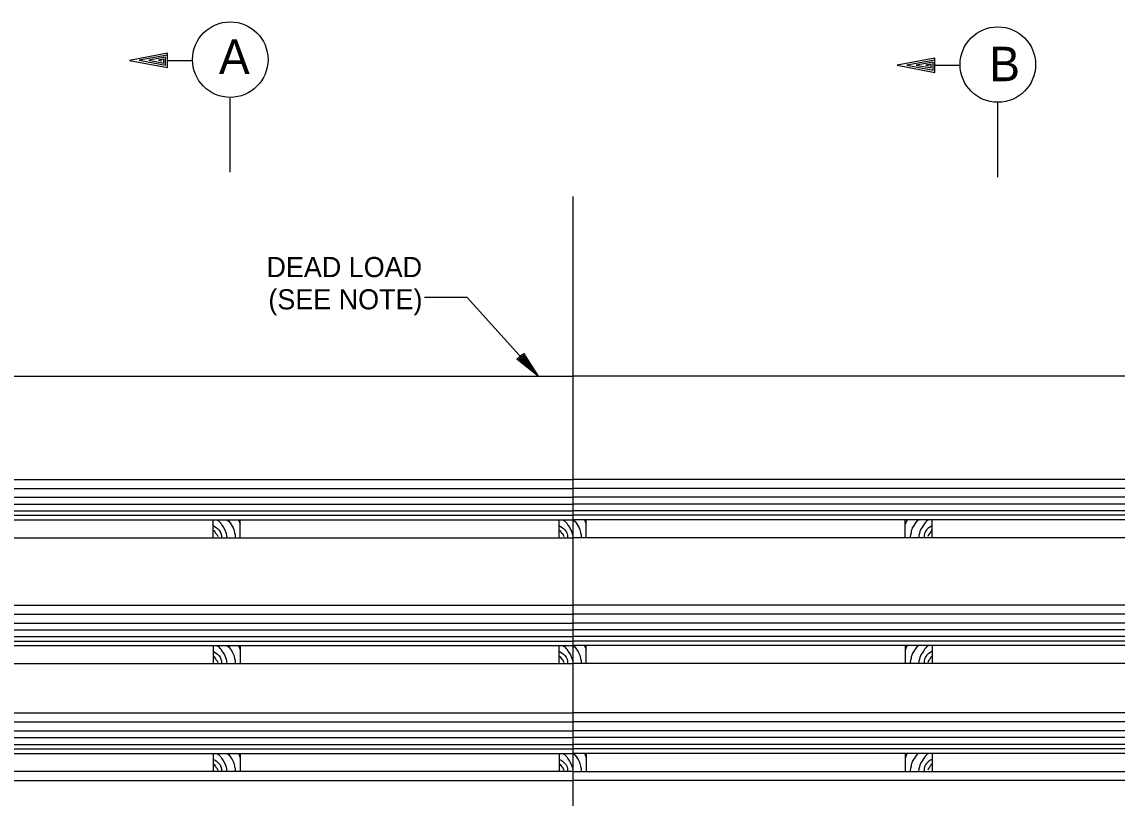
# Model space of a CAD drawing. Extents: x 22378.6 to 22422.6, y 22377.7 to 22411.7.
# Drawn here: x 22385.54 to 22393.16, y 22389.06 to 22394.46 of the extents above; entities that cross this region are included whole.
import ezdxf

# ---------------------------------------------------------------- set-up
doc = ezdxf.new("R2010")
doc.units = 0
for name, color, linetype in [('Level 1', 7, 'Continuous'), ('Level 2', 7, 'Continuous'), ('Level 3', 7, 'Continuous'), ('Level 4', 7, 'Continuous'), ('Level 7', 7, 'Continuous')]:
    doc.layers.add(name, color=color, linetype=linetype)

msp = doc.modelspace()

# ---------------------------------------------------------------- linework, layer by layer
at = {"layer": 'Level 1'}
for p, q in [((22389.3753, 22393.2465), (22389.3753, 22383.2487)), ((22389.1, 22392.0367), (22389.1, 22392.0367)), ((22389.1349, 22391.9982), (22389.1349, 22391.9982)), ((22383.1253, 22391.0607), (22389.3753, 22391.0607)), ((22395.6253, 22391.0607), (22389.3753, 22391.0607)), ((22383.1253, 22391.0295), (22389.3753, 22391.0295)), ((22395.6253, 22391.0295), (22389.3753, 22391.0295)), ((22383.1253, 22390.1857), (22389.3753, 22390.1857)), ((22383.1253, 22390.1545), (22389.3753, 22390.1545)), ((22395.6253, 22390.1857), (22389.3753, 22390.1857)), ((22395.6253, 22390.1545), (22389.3753, 22390.1545)), ((22383.1253, 22389.4357), (22389.3753, 22389.4357)), ((22383.1253, 22389.4045), (22389.3753, 22389.4045)), ((22395.6253, 22389.4357), (22389.3753, 22389.4357)), ((22395.6253, 22389.4045), (22389.3753, 22389.4045))]:
    msp.add_line(p, q, dxfattribs=at)
for points in [[(22389.1349, 22391.9982), (22388.6399, 22392.5435), (22388.3436, 22392.5435)], [(22389.0322, 22392.1575), (22389.1349, 22391.9982), (22388.9863, 22392.1159), (22389.0255, 22392.1515), (22389.1, 22392.0367), (22388.9991, 22392.1166), (22389.0242, 22392.1395), (22389.0664, 22392.0737), (22389.0119, 22392.1174), (22389.0222, 22392.1269), (22389.0314, 22392.1122)], [(22386.9031, 22390.9946), (22386.912, 22390.9913), (22386.9194, 22390.9834), (22386.9269, 22390.9746), (22386.9353, 22390.96), (22386.9443, 22390.9484), (22386.9543, 22390.9328), (22386.961, 22390.916), (22386.9643, 22390.9039), (22386.9684, 22390.89), (22386.9703, 22390.8723)], [(22386.9712, 22390.9964), (22386.9832, 22390.9885), (22386.993, 22390.9767), (22386.9998, 22390.9658), (22387.0067, 22390.9548), (22387.0144, 22390.9417), (22387.0182, 22390.9305), (22387.0215, 22390.9203), (22387.0228, 22390.9077), (22387.0276, 22390.8933), (22387.0283, 22390.881), (22387.0279, 22390.8741)], [(22387.0499, 22390.9978), (22387.0562, 22390.9875), (22387.0624, 22390.9679)], [(22389.3093, 22390.9946), (22389.3182, 22390.9913), (22389.3256, 22390.9834), (22389.3332, 22390.9746), (22389.3415, 22390.96), (22389.3505, 22390.9484), (22389.3605, 22390.9328), (22389.3672, 22390.916), (22389.3705, 22390.9039), (22389.3746, 22390.89), (22389.3765, 22390.8723)], [(22389.3774, 22390.9964), (22389.3894, 22390.9885), (22389.3992, 22390.9767), (22389.406, 22390.9658), (22389.4129, 22390.9548), (22389.4207, 22390.9417), (22389.4244, 22390.9305), (22389.4277, 22390.9203), (22389.429, 22390.9077), (22389.4338, 22390.8933), (22389.4345, 22390.881), (22389.4341, 22390.8741)], [(22389.4561, 22390.9978), (22389.4624, 22390.9875), (22389.4686, 22390.9679)], [(22391.7007, 22390.9978), (22391.6944, 22390.9875), (22391.6882, 22390.9679)], [(22391.7794, 22390.9964), (22391.7674, 22390.9885), (22391.7576, 22390.9767), (22391.7508, 22390.9658), (22391.7438, 22390.9548), (22391.7361, 22390.9417), (22391.7323, 22390.9305), (22391.7291, 22390.9203), (22391.7277, 22390.9077), (22391.723, 22390.8933), (22391.7223, 22390.881), (22391.7226, 22390.8741)], [(22391.8475, 22390.9946), (22391.8385, 22390.9913), (22391.8312, 22390.9834), (22391.8236, 22390.9746), (22391.8152, 22390.96), (22391.8063, 22390.9484), (22391.7963, 22390.9328), (22391.7896, 22390.916), (22391.7862, 22390.9039), (22391.7822, 22390.89), (22391.7803, 22390.8723)], [(22386.8766, 22390.9244), (22386.8821, 22390.9207), (22386.8865, 22390.9136), (22386.8912, 22390.9063), (22386.8943, 22390.9018), (22386.902, 22390.8927), (22386.9063, 22390.8809)], [(22386.8774, 22390.9564), (22386.8878, 22390.9502), (22386.8984, 22390.9434), (22386.9052, 22390.9375), (22386.915, 22390.9286), (22386.9234, 22390.9177), (22386.929, 22390.9038), (22386.9316, 22390.8898), (22386.9321, 22390.878)], [(22389.2828, 22390.9244), (22389.2883, 22390.9207), (22389.2927, 22390.9136), (22389.2975, 22390.9063), (22389.3005, 22390.9018), (22389.3082, 22390.8927), (22389.3125, 22390.8809)], [(22389.2836, 22390.9564), (22389.294, 22390.9502), (22389.3046, 22390.9434), (22389.3114, 22390.9375), (22389.3212, 22390.9286), (22389.3296, 22390.9177), (22389.3352, 22390.9038), (22389.3378, 22390.8898), (22389.3384, 22390.878)], [(22391.8731, 22390.9564), (22391.8628, 22390.9502), (22391.8522, 22390.9434), (22391.8453, 22390.9375), (22391.8356, 22390.9286), (22391.8271, 22390.9177), (22391.8215, 22390.9038), (22391.8189, 22390.8898), (22391.8184, 22390.878)], [(22391.874, 22390.9244), (22391.8685, 22390.9207), (22391.8641, 22390.9136), (22391.8593, 22390.9063), (22391.8563, 22390.9018), (22391.8486, 22390.8927), (22391.8442, 22390.8809)], [(22386.8774, 22390.0814), (22386.8878, 22390.0753), (22386.8984, 22390.0684), (22386.9052, 22390.0625), (22386.915, 22390.0536), (22386.9234, 22390.0427), (22386.929, 22390.0288), (22386.9316, 22390.0149), (22386.9321, 22390.003)], [(22386.9031, 22390.1197), (22386.912, 22390.1164), (22386.9194, 22390.1085), (22386.9269, 22390.0996), (22386.9353, 22390.085), (22386.9443, 22390.0735), (22386.9543, 22390.0578), (22386.961, 22390.041), (22386.9643, 22390.0289), (22386.9684, 22390.0151), (22386.9703, 22389.9973)], [(22386.9712, 22390.1214), (22386.9832, 22390.1136), (22386.993, 22390.1017), (22386.9998, 22390.0908), (22387.0067, 22390.0798), (22387.0144, 22390.0667), (22387.0182, 22390.0555), (22387.0215, 22390.0453), (22387.0228, 22390.0328), (22387.0276, 22390.0183), (22387.0283, 22390.006), (22387.0279, 22389.9992)], [(22387.0499, 22390.1228), (22387.0562, 22390.1125), (22387.0624, 22390.0929)], [(22389.2836, 22390.0814), (22389.294, 22390.0753), (22389.3046, 22390.0684), (22389.3114, 22390.0625), (22389.3212, 22390.0536), (22389.3296, 22390.0427), (22389.3352, 22390.0288), (22389.3378, 22390.0149), (22389.3384, 22390.003)], [(22389.3093, 22390.1197), (22389.3182, 22390.1164), (22389.3256, 22390.1085), (22389.3332, 22390.0996), (22389.3415, 22390.085), (22389.3505, 22390.0735), (22389.3605, 22390.0578), (22389.3672, 22390.041), (22389.3705, 22390.0289), (22389.3746, 22390.0151), (22389.3765, 22389.9973)], [(22389.3774, 22390.1214), (22389.3894, 22390.1136), (22389.3992, 22390.1017), (22389.406, 22390.0908), (22389.4129, 22390.0798), (22389.4207, 22390.0667), (22389.4244, 22390.0555), (22389.4277, 22390.0453), (22389.429, 22390.0328), (22389.4338, 22390.0183), (22389.4345, 22390.006), (22389.4341, 22389.9992)], [(22389.4561, 22390.1228), (22389.4624, 22390.1125), (22389.4686, 22390.0929)], [(22391.7007, 22390.1228), (22391.6944, 22390.1125), (22391.6882, 22390.0929)], [(22391.7794, 22390.1214), (22391.7674, 22390.1136), (22391.7576, 22390.1017), (22391.7508, 22390.0908), (22391.7438, 22390.0798), (22391.7361, 22390.0667), (22391.7323, 22390.0555), (22391.7291, 22390.0453), (22391.7277, 22390.0328), (22391.723, 22390.0183), (22391.7223, 22390.006), (22391.7226, 22389.9992)], [(22391.8475, 22390.1197), (22391.8385, 22390.1164), (22391.8312, 22390.1085), (22391.8236, 22390.0996), (22391.8152, 22390.085), (22391.8063, 22390.0735), (22391.7963, 22390.0578), (22391.7896, 22390.041), (22391.7862, 22390.0289), (22391.7822, 22390.0151), (22391.7803, 22389.9973)], [(22391.8731, 22390.0814), (22391.8628, 22390.0753), (22391.8522, 22390.0684), (22391.8453, 22390.0625), (22391.8356, 22390.0536), (22391.8271, 22390.0427), (22391.8215, 22390.0288), (22391.8189, 22390.0149), (22391.8184, 22390.003)], [(22386.8766, 22390.0494), (22386.8821, 22390.0458), (22386.8865, 22390.0387), (22386.8912, 22390.0313), (22386.8943, 22390.0269), (22386.902, 22390.0177), (22386.9063, 22390.0059)], [(22389.2828, 22390.0494), (22389.2883, 22390.0458), (22389.2927, 22390.0387), (22389.2975, 22390.0313), (22389.3005, 22390.0269), (22389.3082, 22390.0177), (22389.3125, 22390.0059)], [(22391.874, 22390.0494), (22391.8685, 22390.0458), (22391.8641, 22390.0387), (22391.8593, 22390.0313), (22391.8563, 22390.0269), (22391.8486, 22390.0177), (22391.8442, 22390.0059)], [(22386.8774, 22389.3314), (22386.8878, 22389.3253), (22386.8984, 22389.3184), (22386.9052, 22389.3125), (22386.915, 22389.3036), (22386.9234, 22389.2927), (22386.929, 22389.2788), (22386.9316, 22389.2649), (22386.9321, 22389.253)], [(22386.9031, 22389.3697), (22386.912, 22389.3664), (22386.9194, 22389.3585), (22386.9269, 22389.3496), (22386.9353, 22389.335), (22386.9443, 22389.3235), (22386.9543, 22389.3078), (22386.961, 22389.291), (22386.9643, 22389.2789), (22386.9684, 22389.2651), (22386.9703, 22389.2473)], [(22386.9712, 22389.3714), (22386.9832, 22389.3636), (22386.993, 22389.3517), (22386.9998, 22389.3408), (22387.0067, 22389.3298), (22387.0144, 22389.3167), (22387.0182, 22389.3055), (22387.0215, 22389.2953), (22387.0228, 22389.2828), (22387.0276, 22389.2683), (22387.0283, 22389.256), (22387.0279, 22389.2492)], [(22387.0499, 22389.3728), (22387.0562, 22389.3625), (22387.0624, 22389.3429)], [(22389.2836, 22389.3314), (22389.294, 22389.3253), (22389.3046, 22389.3184), (22389.3114, 22389.3125), (22389.3212, 22389.3036), (22389.3296, 22389.2927), (22389.3352, 22389.2788), (22389.3378, 22389.2649), (22389.3384, 22389.253)], [(22389.3093, 22389.3697), (22389.3182, 22389.3664), (22389.3256, 22389.3585), (22389.3332, 22389.3496), (22389.3415, 22389.335), (22389.3505, 22389.3235), (22389.3605, 22389.3078), (22389.3672, 22389.291), (22389.3705, 22389.2789), (22389.3746, 22389.2651), (22389.3765, 22389.2473)], [(22389.3774, 22389.3714), (22389.3894, 22389.3636), (22389.3992, 22389.3517), (22389.406, 22389.3408), (22389.4129, 22389.3298), (22389.4207, 22389.3167), (22389.4244, 22389.3055), (22389.4277, 22389.2953), (22389.429, 22389.2828), (22389.4338, 22389.2683), (22389.4345, 22389.256), (22389.4341, 22389.2492)], [(22389.4561, 22389.3728), (22389.4624, 22389.3625), (22389.4686, 22389.3429)], [(22391.7007, 22389.3728), (22391.6944, 22389.3625), (22391.6882, 22389.3429)], [(22391.7794, 22389.3714), (22391.7674, 22389.3636), (22391.7576, 22389.3517), (22391.7508, 22389.3408), (22391.7438, 22389.3298), (22391.7361, 22389.3167), (22391.7323, 22389.3055), (22391.7291, 22389.2953), (22391.7277, 22389.2828), (22391.723, 22389.2683), (22391.7223, 22389.256), (22391.7226, 22389.2492)], [(22391.8475, 22389.3697), (22391.8385, 22389.3664), (22391.8312, 22389.3585), (22391.8236, 22389.3496), (22391.8152, 22389.335), (22391.8063, 22389.3235), (22391.7963, 22389.3078), (22391.7896, 22389.291), (22391.7862, 22389.2789), (22391.7822, 22389.2651), (22391.7803, 22389.2473)], [(22391.8731, 22389.3314), (22391.8628, 22389.3253), (22391.8522, 22389.3184), (22391.8453, 22389.3125), (22391.8356, 22389.3036), (22391.8271, 22389.2927), (22391.8215, 22389.2788), (22391.8189, 22389.2649), (22391.8184, 22389.253)], [(22386.8766, 22389.2994), (22386.8821, 22389.2958), (22386.8865, 22389.2887), (22386.8912, 22389.2813), (22386.8943, 22389.2769), (22386.902, 22389.2677), (22386.9063, 22389.2559)], [(22389.2828, 22389.2994), (22389.2883, 22389.2958), (22389.2927, 22389.2887), (22389.2975, 22389.2813), (22389.3005, 22389.2769), (22389.3082, 22389.2677), (22389.3125, 22389.2559)], [(22391.874, 22389.2994), (22391.8685, 22389.2958), (22391.8641, 22389.2887), (22391.8593, 22389.2813), (22391.8563, 22389.2769), (22391.8486, 22389.2677), (22391.8442, 22389.2559)]]:
    msp.add_lwpolyline(points, dxfattribs=at)
at = {"layer": 'Level 2'}
for p, q in [((22383.1253, 22391.2795), (22389.3753, 22391.2795)), ((22383.1253, 22391.217), (22389.3753, 22391.217)), ((22395.6253, 22391.2795), (22389.3753, 22391.2795)), ((22395.6253, 22391.217), (22389.3753, 22391.217)), ((22383.1253, 22391.1545), (22389.3753, 22391.1545)), ((22395.6253, 22391.1545), (22389.3753, 22391.1545)), ((22383.1253, 22391.1076), (22389.3753, 22391.1076)), ((22395.6253, 22391.1076), (22389.3753, 22391.1076)), ((22386.8753, 22390.8732), (22386.8753, 22390.9982)), ((22387.0628, 22390.8732), (22387.0628, 22390.9982)), ((22389.2815, 22390.8732), (22389.2815, 22390.9982)), ((22389.469, 22390.8732), (22389.469, 22390.9982)), ((22391.6878, 22390.8732), (22391.6878, 22390.9982)), ((22391.8753, 22390.8732), (22391.8753, 22390.9982)), ((22383.1253, 22390.4045), (22389.3753, 22390.4045)), ((22395.6253, 22390.4045), (22389.3753, 22390.4045)), ((22383.1253, 22390.342), (22389.3753, 22390.342)), ((22395.6253, 22390.342), (22389.3753, 22390.342)), ((22383.1253, 22390.2795), (22389.3753, 22390.2795)), ((22383.1253, 22390.2326), (22389.3753, 22390.2326)), ((22395.6253, 22390.2795), (22389.3753, 22390.2795)), ((22395.6253, 22390.2326), (22389.3753, 22390.2326)), ((22386.8753, 22390.1232), (22386.8753, 22389.9982)), ((22387.0628, 22390.1232), (22387.0628, 22389.9982)), ((22389.2815, 22389.9982), (22389.2815, 22390.1232)), ((22389.469, 22389.9982), (22389.469, 22390.1232)), ((22391.6878, 22390.1232), (22391.6878, 22389.9982)), ((22391.8753, 22390.1232), (22391.8753, 22389.9982)), ((22383.1253, 22389.6545), (22389.3753, 22389.6545)), ((22395.6253, 22389.6545), (22389.3753, 22389.6545)), ((22383.1253, 22389.592), (22389.3753, 22389.592)), ((22395.6253, 22389.592), (22389.3753, 22389.592)), ((22383.1253, 22389.5295), (22389.3753, 22389.5295)), ((22383.1253, 22389.4826), (22389.3753, 22389.4826)), ((22395.6253, 22389.5295), (22389.3753, 22389.5295)), ((22395.6253, 22389.4826), (22389.3753, 22389.4826)), ((22386.8753, 22389.3732), (22386.8753, 22389.2482)), ((22387.0628, 22389.3732), (22387.0628, 22389.2482)), ((22389.2815, 22389.3732), (22389.2815, 22389.2482)), ((22389.469, 22389.3732), (22389.469, 22389.2482)), ((22391.6878, 22389.3732), (22391.6878, 22389.2482)), ((22391.8753, 22389.3732), (22391.8753, 22389.2482)), ((22384.3753, 22389.1857), (22389.3753, 22389.1857)), ((22394.3753, 22389.1857), (22389.3753, 22389.1857))]:
    msp.add_line(p, q, dxfattribs=at)
at = {"layer": 'Level 3'}
for p, q in [((22386.556, 22394.1944), (22386.731, 22394.1944)), ((22391.8936, 22394.16), (22392.0686, 22394.16)), ((22386.9935, 22393.416), (22386.9935, 22393.9323)), ((22392.3311, 22393.3816), (22392.3311, 22393.8979))]:
    msp.add_line(p, q, dxfattribs=at)
for points in [[(22386.556, 22394.2311), (22386.556, 22394.2443), (22386.2935, 22394.1944), (22386.556, 22394.1454), (22386.556, 22394.2311), (22386.3605, 22394.1953), (22386.5434, 22394.1603), (22386.5434, 22394.2168), (22386.4265, 22394.1953), (22386.5311, 22394.1756), (22386.5311, 22394.2019), (22386.4935, 22394.1953), (22386.5184, 22394.1905)], [(22391.8936, 22394.1967), (22391.8936, 22394.2099), (22391.6311, 22394.16), (22391.8936, 22394.111), (22391.8936, 22394.1967), (22391.6981, 22394.1609), (22391.8809, 22394.1259), (22391.8809, 22394.1824), (22391.7641, 22394.1609), (22391.8687, 22394.1412), (22391.8687, 22394.1675), (22391.8311, 22394.1609), (22391.8559, 22394.1561)]]:
    msp.add_lwpolyline(points, dxfattribs=at)
for centre in [(22386.9935, 22394.1994), (22392.3311, 22394.165)]:
    msp.add_circle(centre, 0.2625, dxfattribs=at)
at = {"layer": 'Level 7'}
for p, q in [((22383.1253, 22391.9982), (22389.3753, 22391.9982)), ((22395.6253, 22391.9982), (22389.3753, 22391.9982)), ((22383.1253, 22390.9982), (22389.3753, 22390.9982)), ((22395.6253, 22390.9982), (22389.3753, 22390.9982)), ((22383.1253, 22390.8732), (22389.3753, 22390.8732)), ((22395.6253, 22390.8732), (22389.3753, 22390.8732)), ((22383.1253, 22390.1232), (22389.3753, 22390.1232)), ((22395.6253, 22390.1232), (22389.3753, 22390.1232)), ((22383.1253, 22389.9982), (22389.3753, 22389.9982)), ((22395.6253, 22389.9982), (22389.3753, 22389.9982)), ((22383.1253, 22389.3732), (22389.3753, 22389.3732)), ((22395.6253, 22389.3732), (22389.3753, 22389.3732)), ((22389.3753, 22389.2482), (22384.3753, 22389.2482)), ((22389.3753, 22389.2482), (22394.3753, 22389.2482))]:
    msp.add_line(p, q, dxfattribs=at)

# ---------------------------------------------------------------- texts
at = {"layer": 'Level 3'}
for s, p in [('A', (22386.9147, 22394.0997)), ('B', (22392.2716, 22394.0494))]:
    msp.add_text(s, height=0.2398, dxfattribs=at).set_placement(p)
at = {"layer": 'Level 4'}
for s, p in [('DEAD LOAD', (22387.2453, 22392.6866)), ('(SEE NOTE)', (22387.2586, 22392.462))]:
    msp.add_text(s, height=0.14, dxfattribs=at).set_placement(p)

doc.saveas('drawing.dxf')
